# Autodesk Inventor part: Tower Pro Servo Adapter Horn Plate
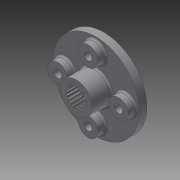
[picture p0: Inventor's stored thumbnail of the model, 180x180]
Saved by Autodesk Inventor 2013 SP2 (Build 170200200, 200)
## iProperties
Created: 2020-02
Part Number: Tower Pro Servo Adapter Horn Plate
Material: Generic
Document SubType Name: Modeling
Designer: DELL
Density: 1 g/cm^3
Author: DELL
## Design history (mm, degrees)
sketch "Sketch1" dims "d2" = 4.61623
  geometry: C1 r 4 at (0, 0); C2 r 2.6 at (0, 0); A1 r 2.308 centre (0, 0) between (0.414, 2.271) and (0.308, 2.287); A2 r 1.037 centre (-0.708, 1.95) between (0.259, 2.327) and (0.255, 2.336); A3 r 0.063 centre (0.317, 2.349) between (0.259, 2.327) and (0.308, 2.287); A4 r 0.062 centre (0.425, 2.332) between (0.414, 2.271) and (0.473, 2.293); A5 r 1.037 centre (1.276, 1.636) between (0.48, 2.301) and (0.473, 2.293); A6 r 1.037 centre (1.276, 1.636) between (0.706, 2.502) and (0.473, 2.293); A7 r 2.6 centre (0, 0) between (0.706, 2.502) and (0.102, 2.598); 2 further points
  constraints: 14 point on circle, 9 centre point, 5 coincident, 6 other
  dimensions: "d3" = 8 diameter of C1; "d8" = 5.2 diameter of C2
extrude "Extrusion1" new body sketch "Sketch1" distance "d4" = 5; taper "d5" = 0 deg
sketch "Sketch5"
  geometry: C1 r 2.6 at (0, 0) reference; 1 further point
extrude "Extrusion4" join sketch "Sketch5" distance "d32" = 1.5; taper "d33" = 0 deg
sketch "Sketch2"
  geometry: L1 (0, -5.6)-(0, 5.6) reference; A1 r 2.6 centre (0, 0) between (0.306, 2.582) and (-0.306, 2.582); A2 r 0.063 centre (-0.055, 2.37) between (-0.108, 2.338) and (-0.053, 2.308); A3 r 0.062 centre (0.055, 2.37) between (0.053, 2.308) and (0.108, 2.338); A4 r 2.308 centre (0, 0) between (0.053, 2.308) and (-0.053, 2.308); A5 r 1.126 centre (1.074, 1.759) between (0.306, 2.582) and (0.108, 2.338); A6 r 1.126 centre (-1.074, 1.759) between (-0.108, 2.338) and (-0.306, 2.582); 1 further point
  constraints: 12 point on circle, 6 centre point, 2 coincident, 1 horizontal alignment, 1 symmetric about line, 1 other
  dimensions: "d9" = 2.6 radius of A1; "d10" = 2.30812 radius of A4; "d11" = 0.0625 radius of A2; "d12" = 0.0625 radius of A3; "d13" = 0.05465 distance from line of A2.centre L1; "d14" = 0.05465 distance from line of L1 A3.centre; "d15" = 2.36999 vertical distance of A2.centre point (0, 0); "d16" = 1.75901 vertical distance of A5.centre point (0, 0); "d17" = 1.07399 horizontal distance of A5.centre point (0, 0); "d18" = 1.12592 radius of A5
extrude "Extrusion2" join sketch "Sketch2" distance "d19" = 3.25; taper "d20" = 0 deg
sketch "Sketch3"
  geometry: C1 r 11 at (0, 0); 1 further point
  constraints: 1 centre point, 1 coincident
  dimensions: "d21" = 22 diameter of C1
extrude "Extrusion3" join sketch "Sketch3" distance "d23" = 2; taper "d24" = 0 deg
sketch "Sketch4"
  geometry: 2 further points
  constraints: 1 coincident
hole "Hole1" sketch "Sketch4" at (0, 0) diameter "d25" = 2.8; stored, may be unused: countersink angle "d29" = 90 deg, drill point angle "d31" = 0 deg; dims "d26" = 6, "d27" = 5, "d28" = 1.75, "d30" = 4
sketch "Sketch6" dims "d37" = 15.5
  geometry: C1 r 2.5 at (7.75, 0); 2 further points
  constraints: 2 horizontal alignment, 1 centre point, 1 coincident, 2 other
  dimensions: "d39" = 5 diameter of C1
extrude "Extrusion5" join sketch "Sketch6" distance "d40" = 2; taper "d41" = 0 deg
sketch "Sketch7"
  geometry: C1 r 2.5 at (0, 0) reference; 2 further points
  constraints: 1 coincident
hole "Hole2" sketch "Sketch7" at (0, 0) diameter "d42" = 2; stored, may be unused: countersink angle "d46" = 90 deg, drill point angle "d48" = 118 deg; dims "d43" = 6, "d44" = 6.5, "d45" = 1, "d47" = 2
pattern_circular "Circular Pattern2" dims angle "d50" = 360 deg
fillet "Fillet1" dims "d52" = 0.5
body "Solid1"
pattern_circular "Circular Pattern1" dims angle "d35" = 360 deg
